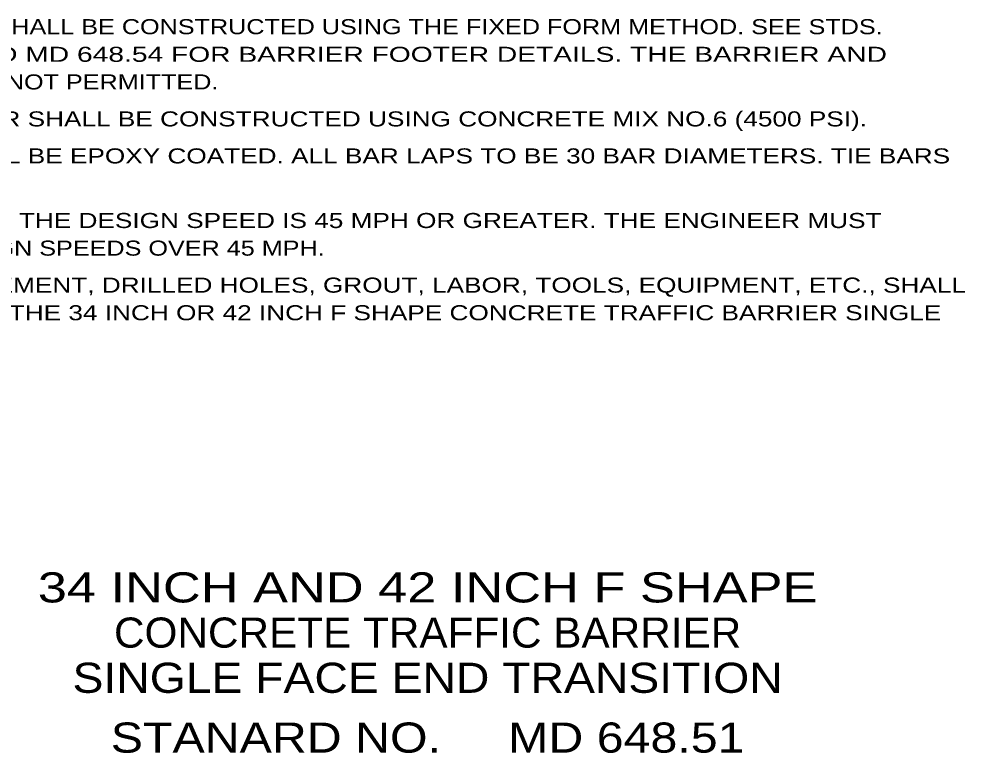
# Model space of a CAD drawing. Extents: x -15.1 to -7.9, y 13.6 to 23.8.
# Drawn here: x -11.694 to -7.924, y 13.588 to 16.513 of the extents above; entities that cross this region are included whole.
import ezdxf
from ezdxf.enums import TextEntityAlignment as Align

# ---------------------------------------------------------------- set-up
doc = ezdxf.new("R2010")
doc.units = 0
doc.header["$LTSCALE"] = 0.024
doc.layers.add('13', color=7, linetype='Continuous', lineweight=53)

msp = doc.modelspace()

# ---------------------------------------------------------------- texts
at = {"layer": '13'}
for s, width, p in [('1. THE TRAFFIC BARRIER END TRANSITION AND BARRIER FOOTER SHALL BE CONSTRUCTED USING THE FIXED FORM METHOD. SEE STDS.', 1.25, (-15.09042, 16.45167)), ('   MD 648.45, MD 648.46, MD 648.47, MD 648.52, MD 648.53, AND MD 648.54 FOR BARRIER FOOTER DETAILS. THE BARRIER AND', 1.4, (-15.09042, 16.34167)), ('   FOOTER SHALL BE CAST SEPARATELY. MONOLITHIC PLACEMENT NOT PERMITTED.', 1.25, (-15.09042, 16.23167)), ('2. THE TRAFFIC BARRIER END TRANSITION AND BARRIER FOOTER SHALL BE CONSTRUCTED USING CONCRETE MIX NO.6 (4500 PSI).', 1.3, (-15.09042, 16.08433)), ('3. ALL REINFORCEMENT BARS, INCLUDING ENDS, AND TIES SHALL BE EPOXY COATED. ALL BAR LAPS TO BE 30 BAR DIAMETERS. TIE BARS', 1.3, (-15.09042, 15.93692)), ('4. THIS TRAFFIC BARRIER END TRANSITION IS PROHIBITED WHEN THE DESIGN SPEED IS 45 MPH OR GREATER. THE ENGINEER MUST', 1.3, (-15.09042, 15.67958)), ('   DETERMINE THE TYPE OF END TREATMENT REQUIRED FOR DESIGN SPEEDS OVER 45 MPH.', 1.25, (-15.09042, 15.56958)), ('5. THE COST OF THE BARRIER END TRANSITION TOE, REINFORCEMENT, DRILLED HOLES, GROUT, LABOR, TOOLS, EQUIPMENT, ETC., SHALL', 1.3, (-15.09042, 15.42217)), ('   BE INCIDENTAL TO THE CONTRACT UNIT PRICE PER EACH FOR THE 34 INCH OR 42 INCH F SHAPE CONCRETE TRAFFIC BARRIER SINGLE', 1.3, (-15.09042, 15.31217))]:
    msp.add_text(s, height=0.06001, dxfattribs=dict(at, width=width)).set_placement(p)
for s, width, p in [('34 INCH AND 42 INCH F SHAPE', 1.3, (-10.06533, 14.18808)), ('CONCRETE TRAFFIC BARRIER', 1.05, (-10.06533, 14.00808)), ('SINGLE FACE END TRANSITION', 1.15, (-10.06533, 13.82808)), ('STANARD NO.     MD 648.51', 1.2, (-10.06525, 13.58983))]:
    msp.add_text(s, height=0.12, dxfattribs=dict(at, width=width)).set_placement(p, align=Align.CENTER)

doc.saveas('drawing.dxf')
